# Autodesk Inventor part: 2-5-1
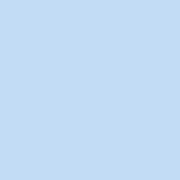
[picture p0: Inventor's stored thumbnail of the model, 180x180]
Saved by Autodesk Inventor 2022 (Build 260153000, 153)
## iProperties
Created: 2021-07
Part Number: 2-5-1
Material: 一般
Document SubType Name: Modeling
Designer: DesignLab
Density: 1 g/cm^3
Appearance: 既定
Author: DesignLab
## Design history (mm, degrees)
